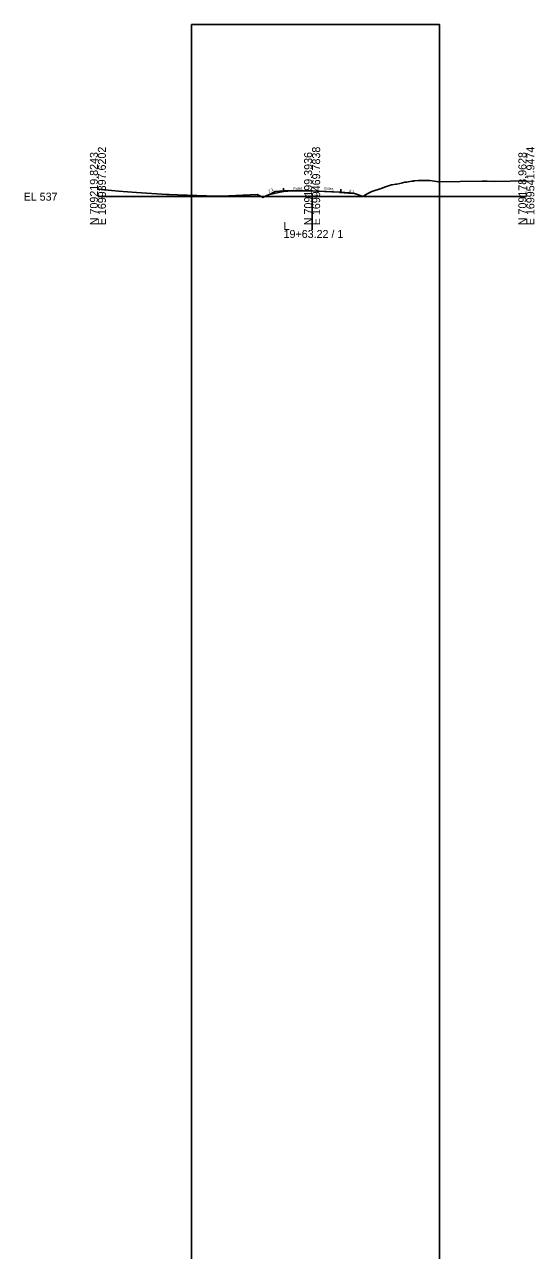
# Model space of a CAD drawing. Extents: x -63 to 1153, y -24 to 9522.
# Drawn here: x 974.3 to 1152.8, y 2131.3 to 2560.2 of the extents above; entities that cross this region are included whole.
import ezdxf

# ---------------------------------------------------------------- set-up
doc = ezdxf.new("R2010")
doc.units = 0
for name, color, linetype in [('Default', 7, 'Continuous'), ('Exist Cross Section Cell', 7, 'Continuous'), ('Exist XS Center Line Elevation Label', 7, 'Continuous'), ('Exist XS Ground Line', 7, 'Continuous'), ('Prop CMT DNC', 7, 'Continuous'), ('Prop CMT Pvmt Surface Overlay', 7, 'Continuous'), ('Prop CMT Slope Grass', 7, 'Continuous'), ('Prop XS Earthwork Shape', 7, 'Continuous'), ('Prop XS EOT Tick Mark', 7, 'Continuous'), ('Prop XS SE Text', 7, 'Continuous'), ('Prop XS Side Slope Text', 7, 'Continuous')]:
    doc.layers.add(name, color=color, linetype=linetype)

msp = doc.modelspace()

# ---------------------------------------------------------------- linework, layer by layer
at = {"layer": 'Exist Cross Section Cell'}
for p, q in [((1000, 2500), (1075, 2500)), ((1075, 2500), (1150, 2500)), ((1075, 2500), (1075, 2488.34))]:
    msp.add_line(p, q, dxfattribs=at)
at = {"layer": 'Exist XS Ground Line'}
msp.add_lwpolyline([(1000, 2502.56), (1007.26, 2501.91), (1013.51, 2501.4), (1024.18, 2500.77), (1024.76, 2500.71), (1025, 2500.7), (1027.91, 2500.61), (1041.42, 2500.15), (1043.34, 2500.14), (1048.31, 2500.4), (1055.79, 2500.7), (1057.38, 2499.94), (1057.76, 2499.72), (1058.68, 2500.13), (1059.96, 2500.71), (1063.75, 2501.52), (1065.43, 2501.89), (1066.52, 2501.9), (1075, 2502), (1075.14, 2502), (1076.62, 2501.93), (1084.57, 2501.51), (1084.61, 2501.48), (1087.69, 2501.18), (1088.17, 2501.17), (1089.33, 2501.16), (1089.71, 2501.13), (1089.78, 2501.1), (1092.85, 2500), (1093.48, 2500.54), (1094.53, 2501.09), (1095.86, 2501.75), (1099.12, 2502.83), (1100.66, 2503.4), (1102.83, 2504.11), (1103.02, 2504.17), (1104.3, 2504.34), (1104.6, 2504.39), (1105.74, 2504.63), (1106.59, 2504.82), (1107.47, 2505.02), (1108.19, 2505.11), (1108.67, 2505.24), (1109.88, 2505.39), (1110.32, 2505.45), (1110.65, 2505.49), (1110.96, 2505.54), (1112.11, 2505.6), (1112.35, 2505.63), (1112.61, 2505.65), (1113.59, 2505.67), (1113.77, 2505.69), (1114.72, 2505.66), (1114.86, 2505.67), (1116.19, 2505.61), (1116.96, 2505.58), (1119.26, 2505.17), (1134.51, 2505.39), (1136.03, 2505.4), (1136.29, 2505.41), (1138.74, 2505.27), (1150, 2505.55)], dxfattribs=at)
at = {"layer": 'Prop CMT DNC'}
msp.add_lwpolyline([(1032.78, 2560.22), (1119.63, 2560.22), (1119.63, 1449.3), (1032.78, 1449.3)], close=True, dxfattribs=at)
at = {"layer": 'Prop CMT Pvmt Surface Overlay'}
for points in [[(1075.01, 2502.06), (1065.01, 2501.98)], [(1075.01, 2502.06), (1085.01, 2501.59)]]:
    msp.add_lwpolyline(points, dxfattribs=at)
at = {"layer": 'Prop CMT Slope Grass'}
for p, q in [((1065, 2501.98), (1065, 2501.8)), ((1085.02, 2501.59), (1085.02, 2501.44)), ((1088.01, 2501.35), (1088.73, 2501.17))]:
    msp.add_line(p, q, dxfattribs=at)
for points in [[(1062.01, 2501.78), (1060.13, 2500.75)], [(1065, 2501.98), (1062.01, 2501.78)], [(1085.02, 2501.59), (1088.01, 2501.35)]]:
    msp.add_lwpolyline(points, dxfattribs=at)
at = {"layer": 'Prop XS Earthwork Shape'}
for points in [[(1065, 2501.98), (1065, 2501.8), (1063.75, 2501.52), (1060.13, 2500.75), (1062.01, 2501.78)], [(1085.02, 2501.59), (1085.02, 2501.44), (1087.69, 2501.18), (1088.17, 2501.17), (1088.73, 2501.17), (1088.01, 2501.35)]]:
    msp.add_lwpolyline(points, close=True, dxfattribs=at)
at = {"layer": 'Prop XS EOT Tick Mark'}
for points in [[(1065.01, 2501.98), (1065, 2502.98)], [(1085.01, 2501.59), (1085.01, 2502.59)]]:
    msp.add_lwpolyline(points, dxfattribs=at)

# ---------------------------------------------------------------- texts
at = {"layer": 'Default'}
msp.add_text('-', height=0.0001, dxfattribs=at).set_placement((1000, 2500))
msp.add_text('-', height=0.0001, dxfattribs=at).set_placement((1000, 2500))
at = {"layer": 'Exist Cross Section Cell'}
for s, p in [('N 709219.8243', (1000, 2490)), ('E 1699397.6202', (1002.8, 2490)), ('N 709199.3936', (1075, 2490)), ('E 1699469.7838', (1077.8, 2490)), ('N 709178.9628', (1150, 2490)), ('E 1699541.9474', (1152.8, 2490))]:
    msp.add_text(s, height=2.8, rotation=90, dxfattribs=at).set_placement(p)
for s, p in [('EL 537', (974, 2498.6)), ('19+63.22 / 1', (1065, 2485.54)), ('L', (1065, 2488.34))]:
    msp.add_text(s, height=2.8, dxfattribs=at).set_placement(p)
at = {"layer": 'Exist XS Center Line Elevation Label'}
msp.add_text('539.00', height=1, dxfattribs=at).set_placement((1072.85, 2499.67))
at = {"layer": 'Prop XS SE Text'}
for rotation, p in [(3.1485, (1068.46, 2502.24)), (356.5635, (1079.24, 2502.43))]:
    msp.add_text('Exist.', height=1, rotation=rotation, dxfattribs=at).set_placement(p)
at = {"layer": 'Prop XS Side Slope Text'}
for s, rotation, p in [('2:1', 26.5651, (1059.9, 2501.34)), ('4:1', 343.6849, (1087.73, 2501.63))]:
    msp.add_text(s, height=1, rotation=rotation, dxfattribs=at).set_placement(p)

doc.saveas('drawing.dxf')
